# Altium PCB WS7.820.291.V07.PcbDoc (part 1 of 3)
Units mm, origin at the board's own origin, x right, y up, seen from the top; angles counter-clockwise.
Board outline 240.26 x 41.75 mm, 4 copper layers (Top Layer, S2, S3, Bottom Layer); 262 components, 157 nets, 756 pads, 1428 vias.
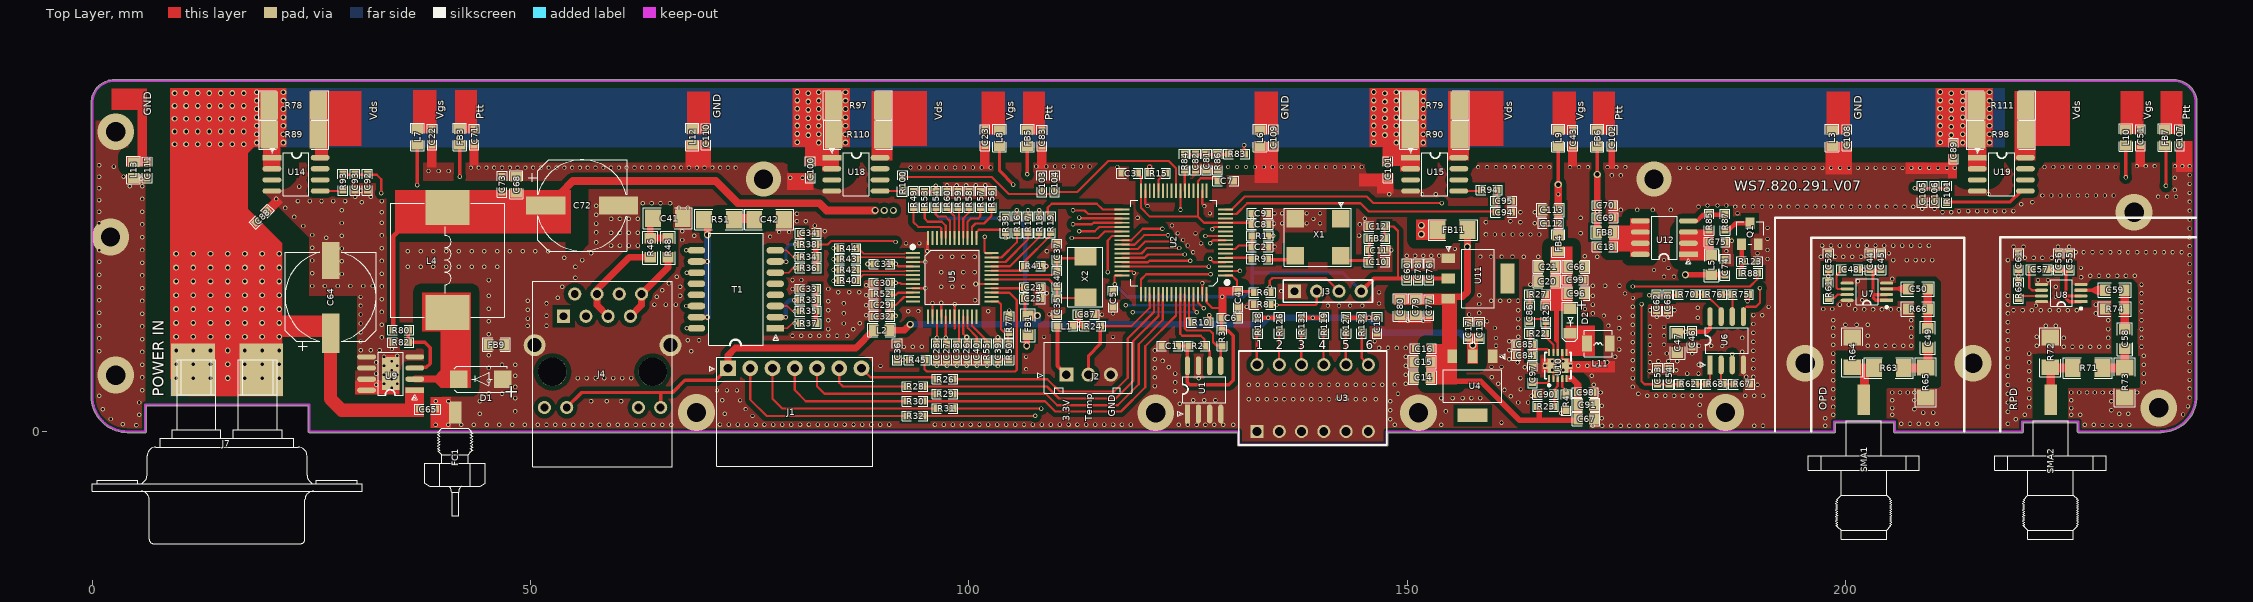
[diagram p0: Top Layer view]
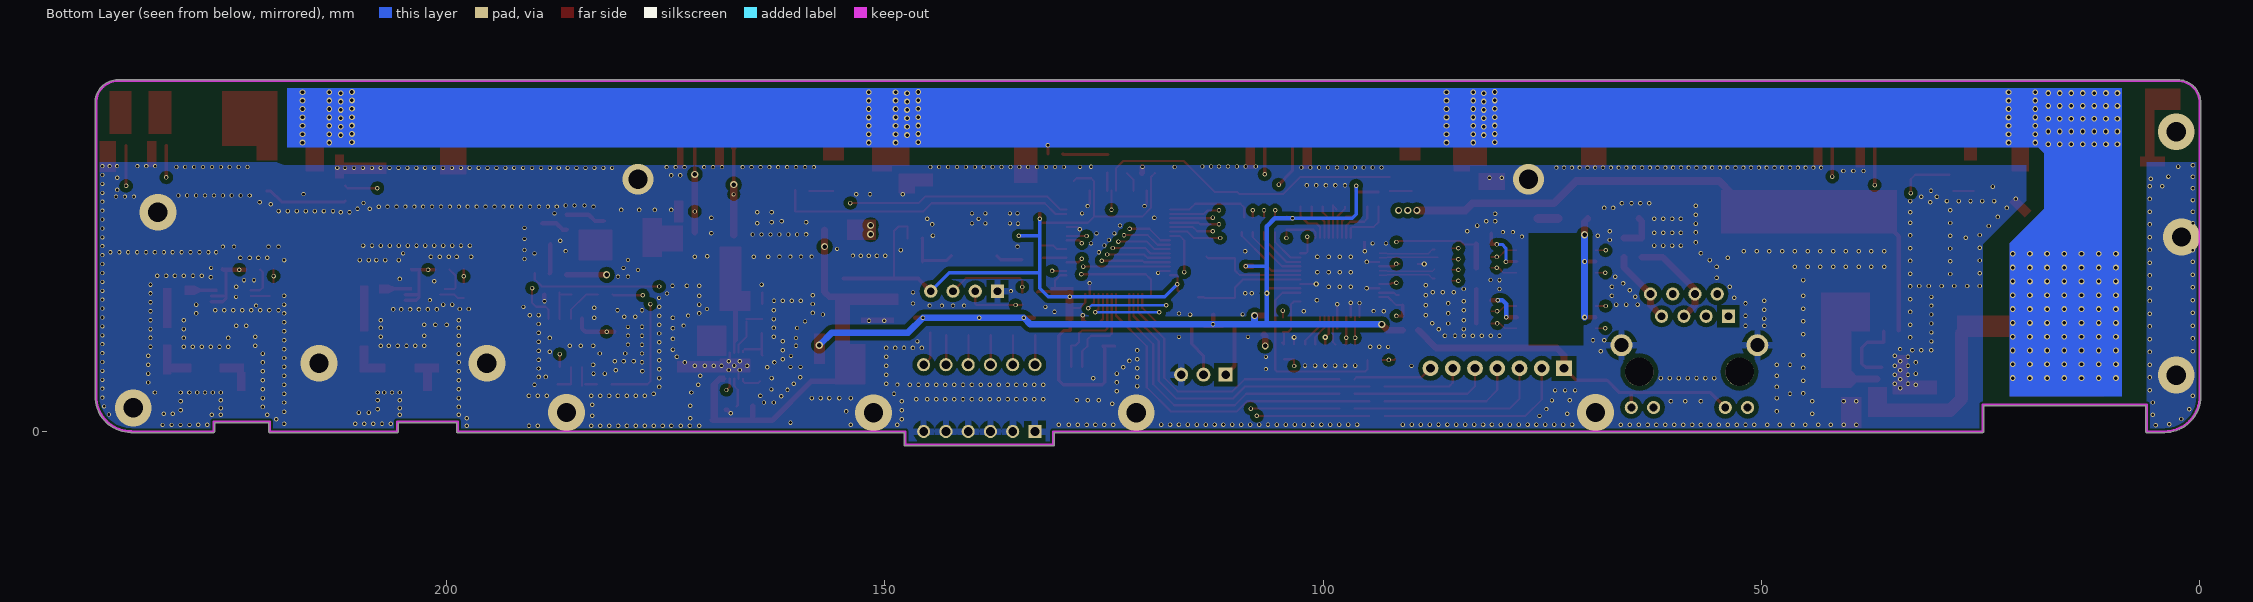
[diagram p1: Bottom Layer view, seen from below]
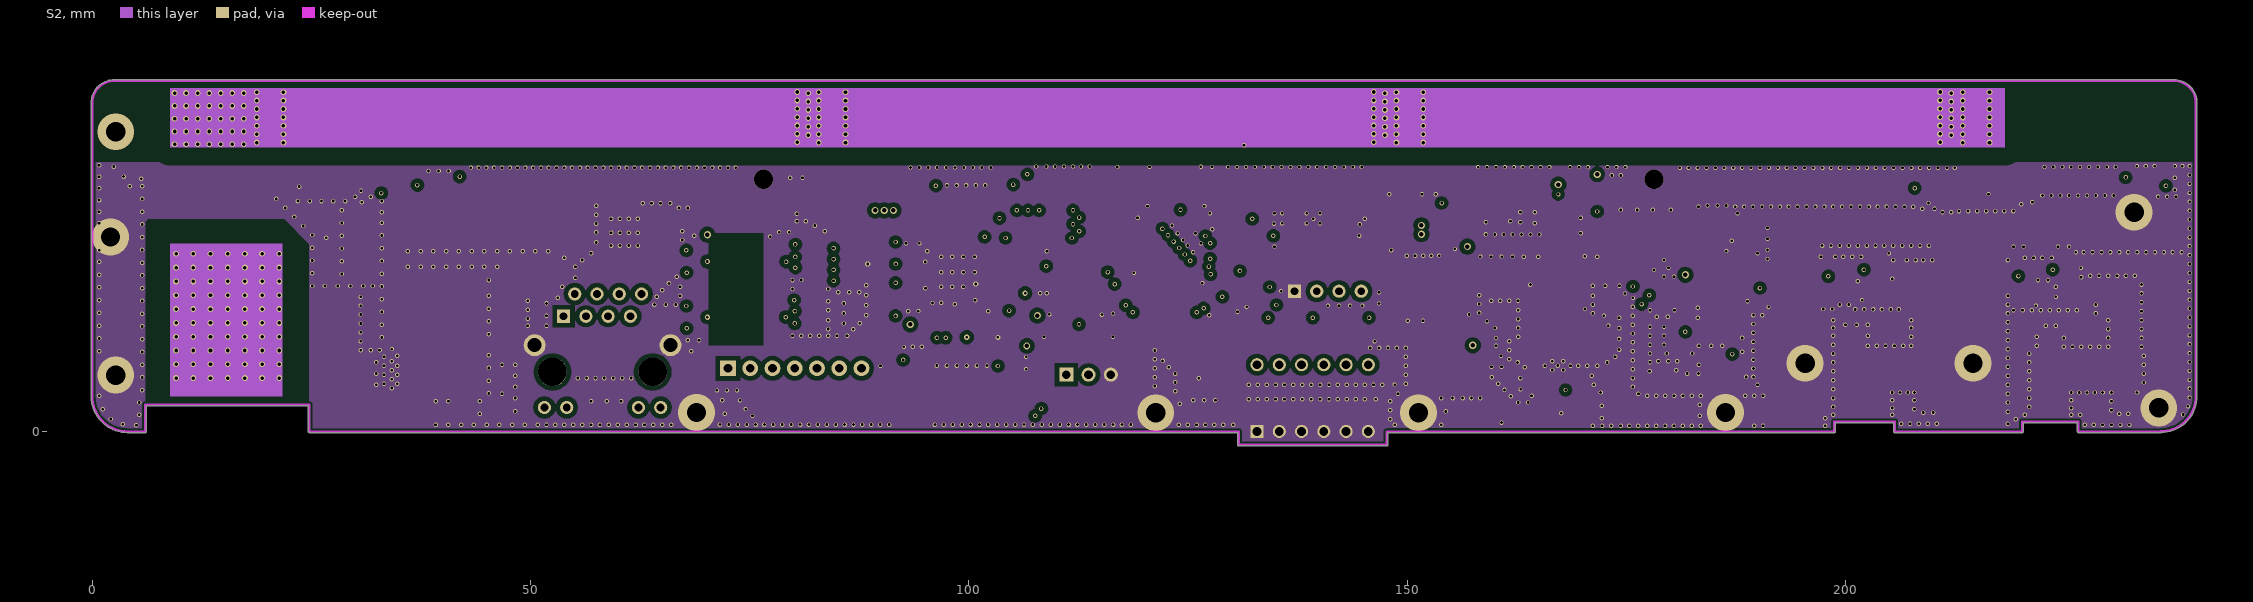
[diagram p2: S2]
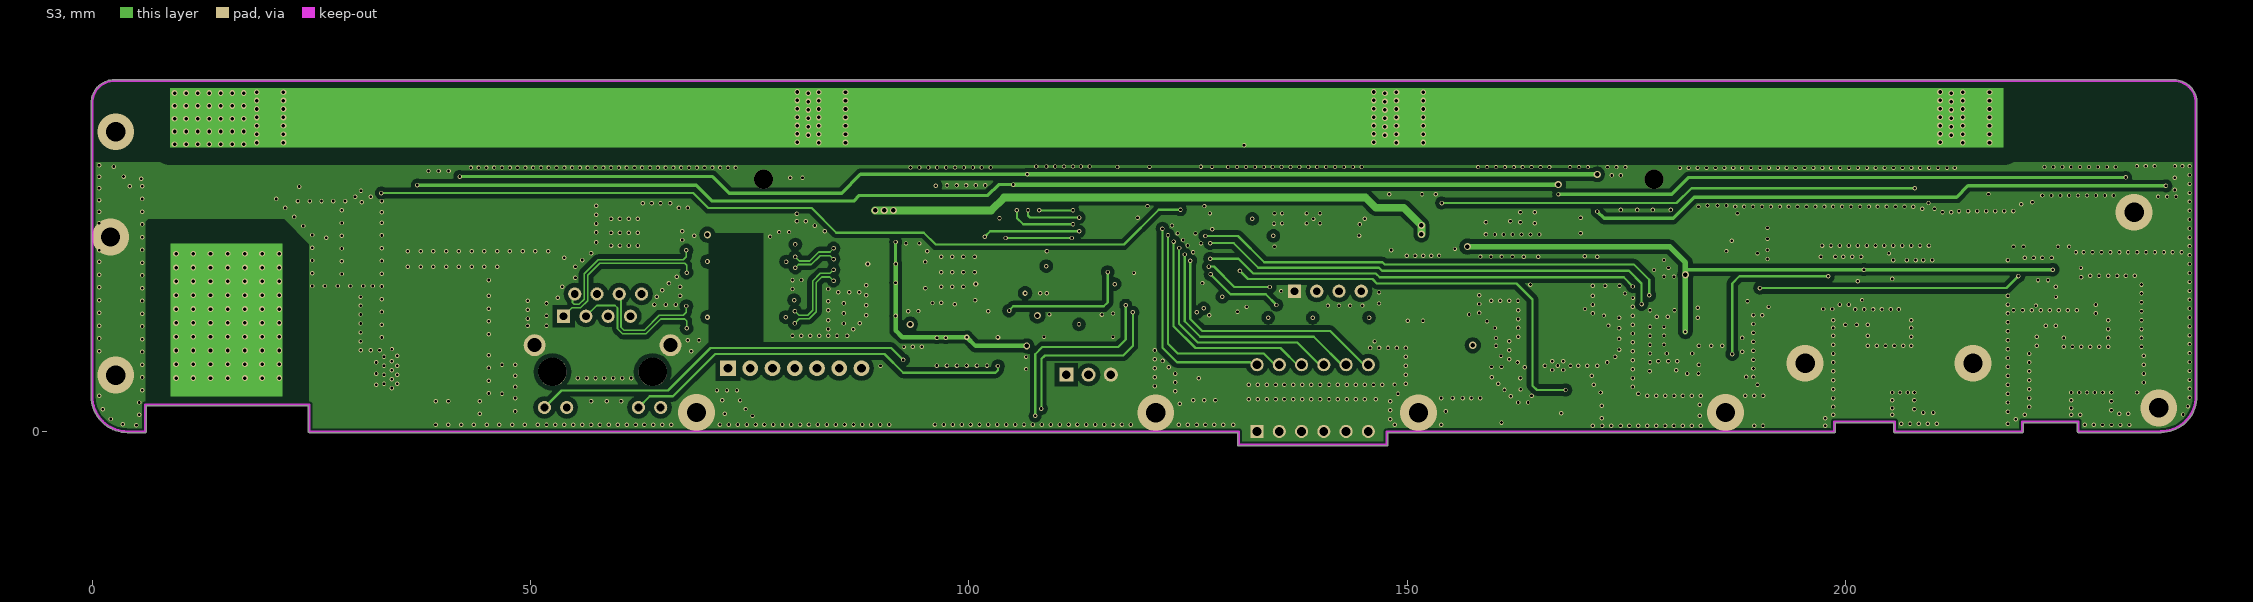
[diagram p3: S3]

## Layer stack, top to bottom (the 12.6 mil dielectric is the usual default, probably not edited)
Top Layer: signal copper 0.0356
Dielectric: core 0.32, FR-4, Dk 4.8
S2: signal copper 0.0356
Dielectric: prepreg 0.32, FR-4, Dk 4.8
S3: signal copper 0.0356
Dielectric: core 0.32, FR-4, Dk 4.8
Bottom Layer: signal copper 0.0356

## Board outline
4.008,-0.127 6.026,-0.127 ccw(c6.026,0) 6.153,0 6.153,2.921 24.638,2.921 24.638,0 ccw(c24.765,0) 24.766,-0.127 130.662,-0.127 130.662,-1.5 ccw(c130.789,-1.5) 130.789,-1.627 147.689,-1.627 ccw(c147.689,-1.5) 147.816,-1.5 147.816,-0.127 198.755,-0.127 ccw(c198.755,0) 198.882,0 198.882,1.019 205.536,1.019 205.536,0 ccw(c205.664,0) 205.664,-0.127 220.193,-0.127 ccw(c220.193,0) 220.32,0 220.32,1.019 226.491,1.019 226.491,0 ccw(c226.619,0) 226.619,-0.127 236,-0.127 ccw(c236,0) 236.057,-0.114 ccw(c236,4.013) 240.127,4.013 240.127,37.503 ccw(c237.508,37.503) 237.544,40.122 ccw(c237.508,40) 237.508,40.127 2.503,40.127 ccw(c2.503,37.492) -0.133,37.492 ccw(c-0.005,37.492) -0.127,37.457 -0.127,4.039 ccw(c0,4.039) -0.119,3.994 ccw(c4.008,4)

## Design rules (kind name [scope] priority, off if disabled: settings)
Clearance Clearance_4 [InNet('28VIN') vs (InPolygon)] p1: gap=2.032
Clearance Clearance_3 [(InPolygon) vs isfill] p2: gap=1.016
Clearance Clearance_2 [All vs OnLayer('Keep-Out Layer')] p3: gap=0.254
Clearance Clearance_1 [All vs (InPolygon)] p4: gap=0.5
Clearance [All] p5: gap=0.203
DiffPairsRouting DiffPair_DiffPairsRouting [All] p1: maxlimit=0.254 minlimit=0.216 mostfreqgap=0.216 maxuncoupledlength=12.7
DiffPairsRouting [All] p2: maxlimit=0.254 minlimit=0.254 mostfreqgap=0.254 maxuncoupledlength=12.7
HoleSize [All] p1: absolutevalues=TRUE maxlimit=76.2 minlimit=0.025 maxpercent=80.000 minpercent=20.000
HoleToHoleClearance [All] p1: gap=0.203 allowstackedmicrovias=TRUE
MatchedLengths DiffPair_MatchedLengths [All] p1: tolerance=25.4 checknetsindiffpair=FALSE checkdiffpairvsdiffpair=TRUE checkothers=FALSE
MinimumSolderMaskSliver [All] p1: minsoldermaskwidth=0
PlaneConnect [isvia] p1: planeconnectstyle=Direct reliefexpansion=0.508 reliefentries=4 reliefconductorwidth=0.254 reliefairgap=0.254
PlaneConnect PlaneConnect_1 [All] p2: planeconnectstyle=Relief reliefexpansion=0.508 reliefentries=4 reliefconductorwidth=0.762 reliefairgap=0.254
PolygonConnect PolygonConnect_1 [isvia] p1: connectstyle=Direct reliefconductorwidth=0.254 reliefentries=4 polygonreliefangle="90 Angle"
PolygonConnect [OnLayer('Bottom Layer')] p2: connectstyle=Relief reliefconductorwidth=0.762 reliefentries=4 polygonreliefangle="90 Angle"
PolygonConnect PolygonConnect_2 [All] p3: connectstyle=Direct reliefconductorwidth=0.254 reliefentries=4 polygonreliefangle="90 Angle"
RoutingVias [All] p1: holewidth=0.305 width=0.406 viastyle="Through Hole" minholewidth=0.305 minwidth=0.381 maxholewidth=0.711 maxwidth=1.27
SilkToSilkClearance [All] p1: silktosilkclearance=0
SilkscreenOverComponentPads [All] p1: minsilkscreentomaskgap=0
SolderMaskExpansion [All] p1: expansion=0.102
Width DiffPair_Width [All] p1: maxlimit=2.54 minlimit=0.191 preferedwidth=0.191
Width [All] p2: maxlimit=1 minlimit=0.191 preferedwidth=0.254 midlayer1_maxwidth=0.254 midlayer2_maxwidth=0.254 minimp=50.000000 maximp=50.000000 favimp=50.000000
21 further rules are at their usual default settings.

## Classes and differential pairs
component class 1-MCU: C1 C2 C3 C4 C5 C6 C7 C8 C9 C10 C11 C12 C87 FB2 J1 J2 J3 L1 L2 R1 R2 R3 R6 R8 R9 R10 R15 R16 R17 R18 R19 R24 R26 R28 R29 R30 R31 R32 R77 R118 R119 R126 R127 R131 R132 TP3 U1 U2 U3 X1
component class 2-RJ45: C24 C25 C26 C27 C28 C29 C30 C31 C32 C33 C34 C35 C36 C37 C38 C39 C40 C41 C42 FB1 FB9 J4 R33 R34 R35 R36 R37 R38 R39 R40 R41 R42 R43 R44 R45 R46 R47 R48 R49 R50 R51 R52 R53 R54 R55 R56 R57 R58 R59 R60 T1 U5 X2
component class 4-POWER: C13 C14 C15 C16 C17 C18 C19 C20 C21 C22 C23 C43 C51 C60 C64 C65 C66 C67 C68 C69 C70 C71 C72 C73 C74 C75 C76 C77 C78 C79 C80 C81 C82 C83 C84 C85 C86 C88 C89 C90 C91 C92 C93 C94 C95 C96 C97 C98 C99 C100 C101 C102 C103 C104 C105 C106 C107 C108 C109 C110 C111 C112 C113 C? D1 D2 FB3 FB4 FB5 FB6 FB7 FB8 FB11 FC1 J7 L3 L4 L5 L6 L7 L8 L9 L10 L11 L12 L13 Q1 R4 R22 R23 R25 R27 R78 R79 R80 R82 R83 R84 R85 R86 R87 R88 R89 R90 R93 R94 R97 R98 R100 R101 R110 R111 R123 U4 U9 U10 U11 U12 U13 U14 U15 U18 U19
component class 3-RF: C44 C45 C46 C47 C48 C49 C50 C52 C53 C54 C55 C56 C57 C58 C59 C61 C62 C63 C118 C119 C120 C122 C123 C124 C125 C126 C127 D3 Q2 Q3 R61 R62 R63 R64 R65 R66 R67 R68 R69 R70 R71 R72 R73 R74 R75 R76 R137 R138 R139 R140 R141 R142 R143 R144 R145 R146 R147 R148 SMA1 SMA2 U6 U7 U8
differential pair RX1: +RX1_P -RX1_N
differential pair RX: +RX_P -RX_N
differential pair TX1: +TX1_P -TX1_N
differential pair TX: +TX_P -TX_N
differential pair W5500_RX1: +W5500_RX1_P -W5500_RX1_N
differential pair W5500_TX1: +W5500_TX1_P -W5500_TX1_N

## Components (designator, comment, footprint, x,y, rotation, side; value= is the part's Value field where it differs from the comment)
C1 "0.1uF" C0603#1 122.936,9.745 r0 top
C2 "0.1uF" C0603#1 133.194,21.051 r180 top
C3 "0.1uF" C0603#1 118.364,29.464 r0 top
C4 "0.1uF" C0603#1 130.717,15.113 r90 top
C5 "0.1uF" C0603#1 116.459,15.113 r90 top
C6 "0.1uF" C0603#1 129.794,12.954 r180 top
C7 "0.1uF" C0603#1 129.308,28.575 r180 top
C8 "0.1uF" C0603#1 133.194,23.622 r180 top
C9 "10uF/6.3V" C0603#1 133.192,24.892 r180 top
C10 "10uF/6.3V" C0603#1 146.566,19.335 r180 top
C11 "0.1uF" C0603#1 146.566,20.677 r0 top
C12 "0.1uF" C0603#1 146.58,23.374 r180 top
C13 "0.1uF" C0603#2 158.242,11.557 r90 top
C14 "10uF/10V" C0805#1 151.74,6.147 r0 top
C15 "10uF/10V" C0805#1 151.74,7.925 r0 top
C16 "0.1uF" C0603#2 151.841,9.449 r180 top
C17 "10uF/6.3V" C0603#2 156.972,11.557 r90 top
C18 "0.1uF" C0603#2 172.593,21.082 r180 top
C19 "10uF/6.3V" C0603#2 146.558,12.122 r270 top
C20 "10uF/10V" C0805#1 165.964,17.145 r0 top
C21 "10uF/10V" C0805#1 165.964,18.796 r0 top
C22 "0.1uF" C0603#2 38.735,33.604 r90 top
C23 "0.1uF" C0603#2 101.854,33.528 r90 top
C24 "0.1uF" C0603#1 107.26,16.446 r180 top
C25 "10uF/6.3V" C0603#1 107.26,15.144 r180 top
C26 "0.1uF" C0603#1 99.767,9.08 r90 top
C27 "0.1uF" C0603#1 97.481,9.08 r90 top
C28 "0.1uF" C0603#1 96.338,9.08 r90 top
C29 "0.1uF" C0603#1 90.09,14.414 r0 top
C30 "0.1uF" C0603#1 90.09,16.954 r0 top
C31 "0.1uF" C0603#1 90.09,19.113 r0 top
C32 "10uF/6.3V" C0603#1 90.09,13.144 r0 top
C33 "10nF" C0603#1 81.661,16.256 r0 top
C34 "22nF" C0603#1 81.686,22.612 r180 top
C35 "18pF" C0603#1 110.054,14.255 r90 top
C36 "1000pF" C0603#1 91.821,9.08 r270 top
C37 "18pF" C0603#1 110.054,20.478 r270 top
C38 "4.7uF" C0603#1 98.624,9.08 r90 top
C39 "1000pF" C0603#1 103.323,9.08 r270 top
C40 "10nF" C0603#1 100.91,9.08 r90 top
C41 "1000pF/2KV" C1206 65.659,24.308 r180 top
C42 "1000pF/2KV" C1206 77.212,24.181 r180 top
C43 "0.1uF" C0603#2 168.91,33.477 r90 top
C44 "100pF" C0603#1 202.819,19.38 r90 top
C45 "0.1uF" C0603#1 204.089,19.38 r90 top
C46 "0.1uF" C0603#1 182.501,10.516 r270 top
C47 "10uF/10V" C0805#2 180.85,10.109 r270 top
C48 "0.1uF" C0603#1 200.533,18.457 r0 top
C49 "100pF" C0805#2 209.423,10.668 r90 top
C50 "100pF" C0805#2 208.296,16.256 r180 top
C51 "0.1uF" C0603#2 233.68,33.528 r90 top
C52 "0.1uF" C0603#1 198.069,19.38 r270 top
C53 "10uF/6.3V" C0603#1 178.602,6.311 r270 top
C54 "0.1uF" C0603#1 179.872,6.311 r270 top
C55 "100pF" C0603#1 225.584,19.38 r90 top
C56 "0.1uF" C0603#1 224.314,19.38 r90 top
C57 "0.1uF" C0603#1 222.123,18.457 r0 top
C58 "100pF" C0805#2 231.902,10.541 r90 top
C59 "100pF" C0805#2 230.759,16.129 r180 top
C60 "10uF/6.3V" C0603#2 149.987,18.212 r90 top
C61 "0.1uF" C0603#1 219.761,19.38 r270 top
C62 "10uF/6.3V" C0603#1 178.475,14.693 r90 top
C63 "0.1uF" C0603#1 179.745,14.693 r90 top
C64 "100uF/63V" ECAP2SM_10R4x10R4#1 27.178,15.367 r90 top
C65 "0.1uF" C0603#1 38.227,2.54 r180 top
C66 "10uF/10V" C0805#1 169.291,18.796 r180 top
C67 "10uF/10V" C0805#1 170.434,1.418 r180 top
C68 "10uF/10V" C0805#1 48.362,28.143 r270 top
C69 "0.1uF" C0603#2 172.593,24.384 r0 top
C70 "10uF" C0603#2 172.593,25.781 r0 top
C71 "0.1uF" C0603#2 43.561,33.604 r270 top
C72 "1000uF/16V" ECAP2SM_10R4x10R4#2 55.88,25.781 r0 top
C73 "0.1uF" C0603#1 46.736,28.194 r270 top
C74 "1uF" C0603#1 186.294,18.726 r90 top
C75 "0.1uF" C0603#1 185.37,21.602 r0 top
C76 "1uF" C0603#1 152.527,18.212 r270 top
C77 "0.1uF" C0603#1 152.502,14.148 r90 top
C78 "10uF/6.3V" C0603#2 151.257,18.212 r90 top
C79 "10uF/10V" C0805#1 150.978,14.148 r90 top
C80 "10uF/10V" C0805#1 149.2,14.148 r90 top
C81 "10uF/6.3V" C0603#1 127.115,30.743 r90 top
C82 "0.1uF" C0603#1 125.845,30.743 r90 top
C83 "0.1uF" C0603#2 108.331,33.477 r270 top
C84 "0.1uF" C0603#2 163.398,8.661 r0 top
C85 "0.1uF" C0603#2 163.398,9.931 r0 top
C86 "10pF" C0603#2 163.999,13.437 r270 top
C87 "0.1uF" C0603#2 113.411,13.335 r0 top
C88 "0.1uF" C0603#1 19.304,24.511 r225 top
C89 "0.1uF" C0603#1 212.344,32.004 r90 top
C90 "0.1uF" C0603#2 165.811,4.216 r180 top
C91 "10uF/10V" C0805#1 170.434,3.048 r180 top
C92 "10uF/6.3V" C0603#1 31.369,28.448 r90 top
C93 "0.1uF" C0603#1 29.972,28.448 r90 top
C94 "10uF/6.3V" C0603#1 161.036,25.019 r180 top
C95 "0.1uF" C0603#1 161.036,26.314 r180 top
C96 "10uF/10V" C0805#1 169.291,15.748 r180 top
C97 "10NF" C0603#2 164.321,6.477 r90 top
C98 "1uF" C0603#2 170.332,4.445 r0 top
C99 "0.1uF" C0603#2 169.189,17.272 r0 top
C100 "0.1uF" C0603#1 81.915,29.845 r90 top
C101 "0.1uF" C0603#1 147.828,29.845 r90 top
C102 "0.1uF" C0603#2 173.355,33.477 r270 top
C103 "10uF/6.3V" C0603#1 108.331,28.245 r270 top
C104 "0.1uF" C0603#1 109.779,28.245 r270 top
C105 "10uF/6.3V" C0603#1 208.788,27.051 r90 top
C106 "0.1uF" C0603#1 210.185,27.051 r90 top
C107 "0.1uF" C0603#2 238.125,33.528 r270 top
C108 "0.1uF" C0603#2 200.182,33.498 r90 top
C109 "0.1uF" C0603#2 134.777,33.498 r90 top
C110 "0.1uF" C0603#2 70.007,33.625 r90 top
C111 "0.1uF" C0603#2 6.253,29.84 r90 top
C112 "0.1uF" C0603#2 166.37,23.749 r180 top
C113 "10uF/10V" C0805#1 166.37,25.273 r0 top
D1 "SS36" DO-214AC 44.323,5.969 r180 top
D2 "SL02" SL02 168.605,12.598 r270 top
FB1 "FB" L0805#1 106.752,12.128 r270 top
FB2 "FB_0603" L0603 146.58,22.032 r0 top
FB3 "FB_0805" L0805#2 41.91,33.604 r90 top
FB4 "FB" L0805#2 167.259,21.463 r90 top
FB5 "FB_0805" L0805#2 106.68,33.477 r90 top
FB6 "FB_0805" L0805#2 171.704,33.477 r90 top
FB7 "FB_0805" L0805#2 236.474,33.528 r90 top
FB8 "FB" L0805#2 172.593,22.733 r180 top
FB9 "open" L0805#2 46.101,9.906 r180 top
FB11 "FB_1206" L1206 155.194,22.987 r0 top
FC1 "CT52-2-63V-2200PF" FC-M4 41.402,2.159 r270 top
J1 "open" "KF2510-7P -2R54-17R8x6R0-wanzhen" 72.517,7.208 r0 top
J2 "XH2.54-3P" XH2.54mm-10R0x7R0--zhizhen 111.125,6.477 r0 top
J3 "Header 4" HDR1X4 137.16,16.002 r0 top
J4 "RJ45插座" RJ45TH-1x1-2R54-LED 58.213,14.414 r0 top
J7 "DB2" DB2TM-VM 15.367,7.017 r180 top locked
L1 "FB_0603" L0603 110.973,12.014 r0 top
L2 "FB_0805" L0805#2 90.043,11.557 r0 top
L3 "FB" L0805#2 198.501,33.477 r90 top
L4 "100uH" PL2SM-12R5x12R5 40.513,19.558 r180 top
L5 "FB_0805" L0805#1 184.735,18.98 r90 top
L6 "FB" L0805#2 133.223,33.477 r90 top
L7 "FB" L0805#2 37.084,33.604 r90 top
L8 "FB" L0805#2 103.505,33.477 r90 top
L9 "FB" L0805#2 167.259,33.477 r90 top
L10 "FB" L0805#2 232.029,33.528 r90 top
L11 "4.7uH" PL2SM-3R0x3R0 171.831,10.033 r180 top
L12 "FB" L0805#2 68.453,33.604 r90 top
L13 "FB" L0805#2 4.699,29.82 r90 top
Q1 "MMBT2222" SOT23-3 189.128,22.572 r270 top
R1 "4.7K" R0603 133.194,22.322 r0 top
R2 "4.7K" R0603 126.031,9.745 r180 top
R3 "4.7K" R0603 128.871,10.668 r90 top
R4 "10K" R0603 168.148,3.302 r270 top
R6 "4.7K" R0603 133.477,15.875 r180 top
R8 "4.7K" R0603 133.477,14.478 r0 top
R9 "30Ω" R0603 133.207,19.665 r180 top
R10 "1K" R0603 126.365,12.446 r180 top
R15 "1K" R0603 121.539,29.464 r0 top
R16 "30Ω" R0603 105.486,23.597 r270 top
R17 "30Ω" R0603 106.756,23.597 r270 top
R18 "30Ω" R0603 108.026,23.597 r270 top
R19 "30Ω" R0603 109.296,23.597 r270 top
R22 "150KΩ" R0603 164.922,11.201 r180 top
R23 "10Ω" R0603 165.811,2.87 r0 top
R24 "4.7K" R0603 114.148,12.014 r0 top
R25 "619KΩ" R0603 165.845,13.437 r270 top
R26 "300Ω" R0603 97.282,5.969 r0 top
R27 "100KΩ" R0603 164.922,15.646 r180 top
R28 "300Ω" R0603 93.853,5.131 r0 top
R29 "300Ω" R0603 97.282,4.293 r0 top
R30 "300Ω" R0603 93.853,3.454 r0 top
R31 "300Ω" R0603 97.282,2.616 r0 top
R32 "300Ω" R0603 93.853,1.778 r0 top
R33 "0Ω" R0603 81.661,14.986 r180 top
R34 "49.9Ω" R0603 81.686,19.914 r0 top
R35 "82Ω" R0603 81.686,13.722 r180 top
R36 "49.9Ω" R0603 81.686,18.669 r0 top
R37 "82Ω" R0603 81.686,12.325 r180 top
R38 "10Ω" R0603 81.686,21.342 r0 top
R39 "4.7K" R0603 104.165,23.597 r90 top
R40 "30Ω" R0603 86.204,17.208 r180 top
R41 "4.7K" R0603 107.26,18.859 r0 top
R42 "30Ω" R0603 86.204,18.435 r180 top
R43 "30Ω" R0603 86.204,19.663 r180 top
R44 "30Ω" R0603 86.204,20.891 r180 top
R45 "300Ω" R0603 94.107,8.156 r0 top
R46 "75Ω" R0805 63.652,20.967 r270 top
R47 "1M" R0603 110.054,17.385 r270 top
R48 "75Ω" R0805 65.684,20.967 r270 top
R49 "4.7K" R0603 93.697,26.479 r90 top
R50 "300Ω" R0603 104.593,9.08 r90 top
R51 "75Ω" R1206 71.497,24.181 r180 top
R52 "12.4K" R0603 90.09,15.684 r0 top
R53 "4.7K" R0603 94.967,26.479 r90 top
R54 "4.7K" R0603 96.237,26.479 r90 top
R55 "1K" R0603 102.053,9.08 r90 top
R56 "1K" R0603 102.587,26.479 r270 top
R57 "1K" R0603 101.317,26.479 r270 top
R58 "1K" R0603 100.047,26.479 r270 top
R59 "1K" R0603 98.777,26.479 r270 top
R60 "1K" R0603 97.507,26.479 r270 top
R61 "1K" R0603 198.069,16.078 r90 top
R62 "0Ω" R0603 182.031,5.388 r180 top
R63 "240Ω" R1206 204.978,7.239 r0 top
R64 "62Ω" R1206 200.787,9.017 r270 top
R65 "62Ω" R1206 209.169,5.588 r90 top
R66 "51Ω" R0805 208.296,13.97 r0 top
R67 "open" R0603 188.185,5.388 r180 top
R68 "0Ω" R0603 185.079,5.388 r180 top
R69 "1K" R0603 219.761,16.078 r90 top
R70 "0Ω" R0603 181.904,15.616 r180 top
R71 "" R1206 227.66,7.239 r0 top
R72 "62Ω" R1206 223.393,9.017 r270 top
R73 "62Ω" R1206 231.902,5.588 r90 top
R74 "51Ω" R0805 230.759,13.97 r0 top
R75 "open" R0603 188.058,15.616 r180 top
R76 "0Ω" R0603 184.981,15.616 r180 top
R77 "0Ω" R0603 104.593,12.192 r270 top
R78 "0.004" R2512 22.987,37.186 r0 top (schematic designator R45)
R79 "0.004" R2512 153.162,37.186 r0 top (schematic designator R47)
R80 "6.2K" R0603 35.179,11.557 r180 top
R82 "2K" R0603 35.179,10.16 r180 top
R83 "24K" R0603 130.556,31.666 r180 top
R84 "1K" C0603#1 124.587,30.743 r90 top
R85 "10K" R0603 184.447,23.888 r270 top
R86 "1.5K" R0603 128.385,30.743 r90 top
R87 "0Ω" R0603 186.294,23.888 r90 top
R88 "1K" R0603 189.099,18.056 r180 top
R89 "0.004" R2512 22.987,33.884 r0 top (schematic designator R198)
R90 "0.004" R2512 153.162,33.884 r0 top (schematic designator R199)
R93 "1K" R0603 28.575,28.448 r90 top
R94 "1K" R0603 159.385,27.559 r0 top
R97 "0.004" R2512 87.376,37.186 r0 top (schematic designator R202)
R98 "0.004" R2512 217.78,33.884 r0 top (schematic designator R102)
R100 "1K" R0603 92.408,28.299 r90 top
R101 "1K" R0603 211.582,27.051 r90 top
R110 "0.004" R2512 87.376,33.884 r0 top (schematic designator R92)
R111 "0.004" R2512 217.78,37.186 r0 top (schematic designator R93)
R118 "4.7K" R0603 133.016,12.122 r90 top
R119 "4.7K" R0603 140.509,12.122 r90 top
R123 "1K" R0603 189.099,19.395 r180 top
R126 "4.7K" R0603 135.429,12.122 r90 top
R127 "4.7K" R0603 143.049,12.122 r90 top
R131 "4.7K" R0603 137.969,12.122 r90 top
R132 "4.7K" R0603 144.827,12.122 r90 top
SMA1 "SMA-50KFD-4" SMA-50KFD-4 202.057,3.611 r270 top (schematic designator SMA2)
SMA2 "SMA-50KFD-4" SMA-50KFD-4 223.376,3.611 r270 top locked (schematic designator SMA3)
T1 "HX1188NL" SOP16-1R27-7R11x12R7 73.428,16.217 r180 top locked
U1 "AT24C02N" SOIC8_1R27_3R9x4R9 126.848,4.75 r90 top
U2 "STM32F103RCT6" LQFP64-0R50-10x10 123.35,21.545 r90 top locked
U3 "2.54mm-6P" CON12TM-2R54-2X6-BOMA 139.239,3.809 r0 top
U4 "LM1117S-3.3" SOT-223 157.48,5.207 r180 top
U5 "W5500" TQFN48-0R5-7X7 98.116,17.589 r0 top locked
U6 "LM358" SOIC8_1R27_3R9x4R9 186.476,10.35 r90 top
U7 "AD8361ARMZ" micro_SOIC8-0R65-3x3 202.477,15.942 r180 top
U8 "AD8361ARMZ" micro_SOIC8-0R65-3x3 224.656,15.783 r180 top locked
U9 "LM2576HVDP-ADJ" SOIC8_1R27_3R9x4R9-1 34.036,6.604 r180 top
U10 "TPS63700DRCR" VSON10-0R5-3x3 167.208,7.518 r90 top
U11 "LM1117S-3.3" SOT-223 158.09,17.45 r270 top
U12 "IRF7240TR" SOIC8_1R27_3R9x4R9 179.364,22.11 r180 top
U14 "MAX4080TASA" SOIC8_1R27_3R9x4R9 23.241,29.337 r0 top
U15 "MAX4080TASA" SOIC8_1R27_3R9x4R9 153.162,29.337 r0 top
U18 "MAX4080TASA" SOIC8_1R27_3R9x4R9 87.122,29.337 r0 top
U19 "MAX4080TASA" SOIC8_1R27_3R9x4R9 217.805,29.337 r0 top
X1 "8M" CRY4SM-5R0x7R0 139.827,22.149 r180 top
X2 "25M" CRY2SM-6R0x3R5 113.306,17.639 r270 top

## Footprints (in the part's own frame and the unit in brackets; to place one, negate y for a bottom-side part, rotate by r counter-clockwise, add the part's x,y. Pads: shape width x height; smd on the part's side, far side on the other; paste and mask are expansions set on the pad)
C0603#1 [mm]
  rect 0.9x0.8 smd: 1(-0.85,0) 2(0.85,0)
  silkscreen extent -1.47,-0.55 1.47,0.55
C0603#2 [mm]
  rect 0.9x0.8 smd: 1(0.85,0) 2(-0.85,0)
  silkscreen extent -1.47,-0.55 1.47,0.55
C0805#1 [mm]
  rect 1.1x1.3 smd: 1(-0.9,0) 2(0.9,0)
  silkscreen extent -1.57,-0.76 1.57,0.76
C0805#2 [mm]
  rect 1.2x1.3 smd: 1(-1.1,0) 2(1.1,0)
  silkscreen extent -1.88,-0.84 1.88,0.84
C1206 [mm]
  rect 1.8x2 smd: 1(-1.7,0) 2(1.7,0)
  silkscreen extent -2.79,-1.19 2.79,1.19
CON12TM-2R54-2X6-BOMA [mm]
  rect 1.5x1.5 hole 1: 1(-6.35,-3.81)
  round 1.5 hole 1: 2(-6.35,3.81) 3(-3.81,-3.81) 4(-3.81,3.81) 5(-1.27,-3.81) 6(-1.27,3.81) 7(1.27,-3.81) 8(1.27,3.81) 9(3.81,-3.81) 10(3.81,3.81) 11(6.35,-3.81) 12(6.35,3.81)
  silkscreen extent -8.45,-5.36 8.45,5.36
CRY2SM-6R0x3R5 [mm]
  rect 2x2.5 smd: 1(-2.3,0) 2(2.3,0)
  silkscreen extent -3.4,-2.03 3.4,1.97
CRY4SM-5R0x7R0 [mm]
  rect 2x2 smd: 1(-2.6,-2.1) 2(2.6,-2.1) 3(2.6,2.1) 4(-2.6,2.1)
  silkscreen extent -3.81,-4.02 3.81,3.33
DB2TM-VM [mm] "DB2"
  rect 5x6 smd: 1(-3.9,0) 2(3.9,0)
  Top Overlay keep-out lines w0.1: -1.298,2.812 -5.698,2.812
  silkscreen extent -15.4,-1.19 15.4,19.81
DO-214AC [mm]
  rect 2x2 smd: 1(-2.5,0) 2(2.5,0)
  silkscreen extent -3.04,-1.49 3.04,1.49
ECAP2SM_10R4x10R4#1 [mm]
  rect 4.5x2 smd: 1(-4.15,0)
  rect 4.191x2 smd: 2(4.15,0)
  silkscreen extent -6.16,-5.21 5.08,5.21
ECAP2SM_10R4x10R4#2 [mm]
  rect 4.5x2 smd: 1(-4.15,0) 2(4.15,0)
  silkscreen extent -6.16,-5.21 5.08,5.21
FC-M4 [mm] "一对"
  rect 2.5x1.4 smd: 1(0,0)
  silkscreen extent 1.8,-3.48 11.77,3.44
HDR1X4 [mm] "Connector; Header; 4 Position"
  rect 1.5x1.5 hole 0.9: 1(0,0)
  round 1.5 hole 0.9: 2(2.54,0) 3(5.08,0) 4(7.62,0)
  silkscreen extent -1.27,-1.27 8.89,1.27
"KF2510-7P -2R54-17R8x6R0-wanzhen" [mm]
  rect 1.8x1.8 hole 1: 1(0,0)
  round 1.8 hole 1: 2(2.54,0) 3(5.08,0) 4(7.62,0) 5(10.16,0) 6(12.7,0) 7(15.24,0)
  silkscreen extent -2.12,-11.2 16.56,1.24
L0603 [mm]
  rect 0.9x0.8 smd: 1(-0.85,0) 2(0.85,0)
  silkscreen extent -1.47,-0.55 1.47,0.55
L0805#1 [mm]
  rect 1.2x1.3 smd: 1(-1.1,0) 2(1.1,0)
  silkscreen extent -1.88,-0.84 1.88,0.84
L0805#2 [mm]
  rect 1.1x1.3 smd: 1(-0.9,0) 2(0.9,0)
  silkscreen extent -1.57,-0.76 1.57,0.76
L1206 [mm]
  rect 1.8x2 smd: 1(-1.7,0) 2(1.7,0)
  silkscreen extent -2.79,-1.19 2.79,1.19
LQFP64-0R50-10x10 [mm] "STM32F103RC"
  rect 0.22x1.7 smd: 1(-3.731,-5.941) 2(-3.231,-5.941) 3(-2.731,-5.941) 4(-2.231,-5.941) 5(-1.731,-5.941) 6(-1.231,-5.941) 7(-0.731,-5.941) 8(-0.231,-5.941) 9(0.269,-5.941) 10(0.769,-5.941) 11(1.269,-5.941) 12(1.769,-5.941) 13(2.269,-5.941) 14(2.769,-5.941) 15(3.269,-5.941) 16(3.769,-5.941) 33(3.769,5.861) 34(3.269,5.861) 35(2.769,5.862) 36(2.269,5.862) 37(1.769,5.862) 38(1.269,5.862) 39(0.769,5.862) 40(0.269,5.862) 41(-0.231,5.862) 42(-0.731,5.862) 43(-1.231,5.862) 44(-1.731,5.862) 45(-2.231,5.862) 46(-2.731,5.862) 47(-3.231,5.862) 48(-3.731,5.861)
  rect 1.7x0.22 smd: 17(5.917,-3.793) 18(5.917,-3.293) 19(5.917,-2.793) 20(5.917,-2.293) 21(5.917,-1.793) 22(5.917,-1.293) 23(5.917,-0.793) 24(5.917,-0.293) 25(5.917,0.207) 26(5.917,0.707) 27(5.917,1.207) 28(5.917,1.707) 29(5.917,2.207) 30(5.917,2.707) 31(5.917,3.207) 32(5.917,3.707) 49(-5.886,3.713) 50(-5.886,3.213) 51(-5.886,2.713) 52(-5.886,2.213) 53(-5.886,1.713) 54(-5.886,1.213) 55(-5.886,0.713) 56(-5.886,0.213) 57(-5.886,-0.287) 58(-5.886,-0.787) 59(-5.886,-1.287) 60(-5.886,-1.787) 61(-5.886,-2.286) 62(-5.886,-2.786) 63(-5.886,-3.287) 64(-5.886,-3.786)
  silkscreen extent -4.92,-6.32 4.86,4.85
micro_SOIC8-0R65-3x3 [mm] "检波器"
  rect 1.5x0.35 smd: 1(-2.25,0.975)
  oval 1.5x0.35 smd: 2(-2.25,0.325) 3(-2.25,-0.325) 4(-2.25,-0.975) 5(2.25,-0.975) 6(2.25,-0.325) 7(2.25,0.325) 8(2.25,0.975)
  silkscreen extent -2.38,-1.5 1.23,1.87
PL2SM-3R0x3R0 [mm]
  rect 1.1x1.8 smd: 1(-1.3,0) 2(1.3,0)
  silkscreen extent -1.6,-1.5 1.6,1.5
PL2SM-12R5x12R5 [mm]
  rect 5x4 smd: 1(0,6) 2(0,-6)
  silkscreen extent -6.5,-6.5 6.5,6.5
R0603 [mm]
  rect 0.9x0.8 smd: 1(-0.85,0) 2(0.85,0)
  silkscreen extent -1.47,-0.55 1.47,0.55
R0805 [mm]
  rect 1.2x1.3 smd: 1(-1.1,0) 2(1.1,0)
  silkscreen extent -1.88,-0.84 1.88,0.84
R1206 [mm]
  rect 1.8x2 smd: 1(-1.7,0) 2(1.7,0)
  silkscreen extent -2.79,-1.19 2.79,1.19
R2512 [mm]
  rect 2x3.2 smd: 1(-2.8,0) 2(2.8,0)
  silkscreen extent -3.99,-1.7 3.91,1.7
RJ45TH-1x1-2R54-LED [mm]
  rect 1.5x1.5 hole 0.9: 1(-4.445,-1.27)
  round 1.5 hole 0.9: 2(-3.175,1.27) 3(-1.905,-1.27) 4(-0.635,1.27) 5(0.635,-1.27) 6(1.905,1.27) 7(3.175,-1.27) 8(4.445,1.27) 9(-6.63,-11.68) 10(-4.09,-11.68) 11(4.09,-11.68) 12(6.63,-11.68)
  round 2.5 hole 1.6: 13(-7.75,-4.57) 14(7.75,-4.57)
  round 3.25 hole 3.25 unplated: 15(-5.715,-7.62) 16(5.715,-7.62)
  silkscreen extent -7.94,-18.42 7.94,2.73
SL02 [mm]
  rect 1.2x1.5 smd: 1(-1.4,0) 2(1.4,0)
  silkscreen extent -2.16,-0.9 2.28,0.9
SMA-50KFD-4 [mm] "SMA-JB3C"
  rect 3.5x1.4 smd: 1(0,0.06)
  silkscreen extent 2.37,-6.29 15.9,6.41
SOIC8_1R27_3R9x4R9 [mm]
  rect 2.15x0.6 smd: 1(-2.75,1.905)
  oval 2.15x0.6 smd: 2(-2.75,0.635) 3(-2.75,-0.635) 4(-2.75,-1.905) 5(2.75,-1.905) 6(2.75,-0.635) 7(2.75,0.635) 8(2.75,1.905)
  silkscreen extent -3.02,-2.45 1.47,2.99
SOIC8_1R27_3R9x4R9-1 [mm]
  rect 2.15x0.6 smd: 1(-2.75,1.905)
  oval 2.15x0.6 smd: 2(-2.75,0.635) 3(-2.75,-0.635) 4(-2.75,-1.905) 5(2.75,-1.905) 6(2.75,-0.635) 7(2.75,0.635) 8(2.75,1.905)
  rect 2x3.8 smd: 9(0,0)
  silkscreen extent -3.02,-2.45 1.47,2.99
SOP16-1R27-7R11x12R7 [mm]
  rect 2x0.76 smd: 1(-4.5,4.445)
  oval 2x0.76 smd: 2(-4.5,3.175) 3(-4.5,1.905) 4(-4.5,0.635) 5(-4.5,-0.635) 6(-4.5,-1.905) 7(-4.5,-3.175) 8(-4.5,-4.445) 9(4.5,-4.445) 10(4.5,-3.175) 11(4.5,-1.905) 12(4.5,-0.635) 13(4.5,0.635) 14(4.5,1.905) 15(4.5,3.175) 16(4.5,4.445)
  silkscreen extent -4.84,-6.4 3.1,6.4
SOT23-3 [mm]
  rect 1.3x1 smd: 1(1.2,-0.95) 2(1.2,0.95) 3(-1.2,0)
  silkscreen extent -1.34,-1.5 1.2,1.5
SOT-223 [mm]
  rect 1.1x1.55 smd: 1(-2.3,-3.375) 2(0,-3.375) 3(2.3,-3.375)
  rect 3.45x1.55 smd: 4(0,3.375)
  silkscreen extent -3.7,-3.65 3.35,1.85
TQFN48-0R5-7X7 [mm]
  rect 1.6x0.22 smd: 1(-4.5,2.75) 2(-4.5,2.25) 3(-4.5,1.75) 4(-4.5,1.25) 5(-4.5,0.75) 6(-4.5,0.25) 7(-4.5,-0.25) 8(-4.5,-0.75) 9(-4.5,-1.25) 10(-4.5,-1.75) 11(-4.5,-2.25) 12(-4.5,-2.75) 25(4.5,-2.75) 26(4.5,-2.25) 27(4.5,-1.75) 28(4.5,-1.25) 29(4.5,-0.75) 30(4.5,-0.25) 31(4.5,0.25) 32(4.5,0.75) 33(4.5,1.25) 34(4.5,1.75) 35(4.5,2.25) 36(4.5,2.75)
  rect 0.22x1.6 smd: 13(-2.75,-4.5) 14(-2.25,-4.5) 15(-1.75,-4.5) 16(-1.25,-4.5) 17(-0.75,-4.5) 18(-0.25,-4.5) 19(0.25,-4.5) 20(0.75,-4.5) 21(1.25,-4.5) 22(1.75,-4.5) 23(2.25,-4.5) 24(2.75,-4.5) 37(2.75,4.5) 38(2.25,4.5) 39(1.75,4.5) 40(1.25,4.5) 41(0.75,4.5) 42(0.25,4.5) 43(-0.25,4.5) 44(-0.75,4.5) 45(-1.25,4.5) 46(-1.75,4.5) 47(-2.25,4.5) 48(-2.75,4.5)
  silkscreen extent -4.72,-3.06 3.06,3.65
VSON10-0R5-3x3 [mm] "QFN, 12-Leads, Body 4.0x4.0mm (max), Pitch 0.50mm, IPC Low Density"
  rect 0.8x0.25 smd: 1(-1.5,1) 2(-1.5,0.5) 3(-1.5,0) 4(-1.5,-0.5) 5(-1.5,-1) 6(1.5,-1) 7(1.5,-0.5) 8(1.5,0) 9(1.5,0.5) 10(1.5,1)
  rect 0.25x0.8 smd: 11(-0.25,1.3) 11(-0.25,-1.3) 11(0.25,1.3) 11(0.25,-1.3)
  rect 1.65x2.4 smd: 11(0,0)
  silkscreen extent -2.37,-1.5 1.5,1.5
XH2.54mm-10R0x7R0--zhizhen [mm]
  rect 1.6x1.6 hole 1: 1(0,0)
  round 1.6 hole 1: 2(2.54,0) 3(5.08,0)
  silkscreen extent -3.31,-2.1 7.5,3.7

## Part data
C1 C2 C3 C4 C5 C6 C7 C8 C11 C12 C16 C24 C26 C27 C28 C29 C30 C31 C45 C46 C48 C52 C54 C56 C57 C61 C63 C65 C73 C75 C77 C82 C88 C89 C93 C95 C100 C101 C104 C106: library part 0.1uF贴片电容, "贴片电容_GRM188R71H104KA01D_0.1uF±10%,50V,0603"
C9 C10 C17 C19 C25 C32 C53 C60 C62 C78 C81 C92 C94 C103 C105: library part 10uF贴片电容, "贴片电容_GRM188R60J106ME47D_10uF±20%,6.3V,0603"
C13 C74 C76: library part 1uF贴片电容, "贴片电容_GRM188R61A105KA61D_1uF±10%,10V,0603"
C14 C15 C20 C21 C47 C66 C67 C68 C79 C80 C91 C96 C113: library part 10uF贴片电容, "贴片电容_GRM21BR61A106KE19L_10uF±10%,10V,0805"
C18 C22 C23 C43 C51 C69 C71 C83 C84 C85 C87 C90 C99 C102 C107 C108 C109 C110 C111 C112: "GRM188R71H104KA01D"
C33 C40: library part 0.1uF贴片电容, "贴片电容_10nF±10%,50V,0603"
C34: library part 27nF贴片电容, "贴片电容_22nF±5%,50V,0603"
C35 C37: library part 20pF贴片电容, "贴片电容_18pF±5%,50V,0603"
C36 C39: library part 1000pF贴片电容, "贴片电容_GRM188R71H102KA01_1000pF±10%,50V,0603"
C38: library part 1uF贴片电容, "贴片电容_4.7uF±10%,50V,0603"
C41 C42: library part 10uF贴片电容, "贴片电容_1000pF/2KV"
C44 C55: library part 220pF贴片电容, "贴片电容_100pF±10%,50V,0603"
C49 C50 C58 C59: library part 100pF贴片电容, "贴片电容_GRM2165C1H101JA01D_100pF±5%,50V,0805"
C64: "贴片电解电容_VEJ101M1JTR-1010_100uF/63V,±20%,表贴D10*H10"
C70 C98: library part 0.1uF
C72: "贴片电解电容_VE102M1CTR-1010_1000uF/16V,±20%,表贴10*10"
C86: library part 10pF贴片电容, "贴片电容_0603CG100J500NT_10pF±5%,50V,0603"
C97: library part 0.1uF, "0603,10NF,50V,±10％,X7R"
D1: library part 肖特基整流二极管_SS36, "肖特基整流二极管_SS36_封装SMA,3A/60V"
D2: library part 肖特基整流二极管_SS36, "肖特基整流二极管_SL02_1.1A/20V"
FB1 FB3 FB4 FB5 FB6 FB7 FB8 FB9 L1 L2 L3 L5 L6 L7 L8 L9 L10 L12 L13: library part 0805贴片磁珠, "贴片磁珠_600R,0805"
FB2: library part 0603贴片磁珠, "贴片磁珠_100R,0603"
FB11: library part 1206贴片磁珠, "贴片磁珠_30R,6A,1206"
FC1: library part M4穿心电容, "穿心电容_CT52-2-63V-2200PF_M4,2200PF,63V"
J1: library part KF2510-7P连接器, "连接器_KF2510-7P_直插,间距2.54mm"
J2: "连接器_XH2.54-3P_弯针,间距2.54mm"
J3: "Header, 4-Pin"
J4: library part RJ45弯脚带灯, "RJ45插座_1*1,带左黄右绿灯,弯脚"
J7: library part DB2公头座子, "连接器_DB2公头,电源接头"
L4: library part 100uH贴片功率电感, "贴片功率电感_SLF12575T-101M1R9-PF_100uH±20%,额定电流1.9A,12.5x12.5"
L11: library part SLF6025T-100M1R0-PF, "SPM3010T-4R7M-LR"
Q1: "NPN三极管_MMBT2222_表贴SOT23"
R1 R2 R3 R6 R24 R39 R41 R49 R53 R54: library part 4.7K贴片电阻, "贴片电阻_4.7K±5%,0603"
R4 R85: library part 10K贴片电阻, "贴片电阻_10K±5%,0603"
R8 R10 R15 R55 R56 R57 R58 R59 R60 R61 R69 R84 R88 R93 R94 R100 R101 R123: library part 1K贴片电阻, "贴片电阻_1K±5%,0603"
R9 R16 R17 R18 R19 R40 R42 R43 R44: library part 30Ω贴片电阻, "贴片电阻_30Ω±5%,0603"
R22 R25 R27: library part 10Ω贴片电阻
R23 R38: library part 10Ω贴片电阻, "贴片电阻_10Ω±5%,0603"
R26 R28 R29 R30 R31 R32 R45 R50: library part 300Ω贴片电阻, "贴片电阻_300Ω±5%,0603"
R33 R62 R68 R70 R76 R77 R87: library part 0Ω贴片电阻, "贴片电阻_0Ω±5%,0603"
R34 R36: library part 51Ω贴片电阻, "贴片电阻_49.9Ω±1%,0603"
R35 R37: library part 51Ω贴片电阻, "贴片电阻_82Ω±1%,0603"
R46 R48: library part 75Ω贴片电阻, "贴片电阻_75Ω±5%,0805"
R47: library part 1M贴片电阻, "贴片电阻_1M±5%,0603"
R51: library part 75Ω贴片电阻, "贴片电阻_75Ω±5%,1206"
R52: library part 12K贴片电阻, "贴片电阻_12.4K±1%,0603"
R63: library part 300Ω贴片电阻
R64 R65 R72 R73: library part 62Ω贴片电阻
R66 R74: library part 51Ω贴片电阻, "贴片电阻_51Ω±5%,0805"
R67 R75: library part 0Ω贴片电阻
R71: library part 300Ω贴片电阻, "贴片电阻_300Ω±5%,0805"
R78 R79 R89 R90 R97 R98 R110 R111: library part 0.004Ω检流电阻-大封装, "贴片电阻_LR12DTDSR004_0.004±5%,2W,2512"
R80: library part 6.2K贴片电阻, "贴片电阻_6.2K±5%,0603"
R82: library part 2K贴片电阻, "贴片电阻_2K±5%,0603"
R83: library part 12.4K贴片电阻
R86: library part 1.5K贴片电阻, "贴片电阻_1.5K±5%,0603"
R118 R119 R126 R127 R131 R132: library part 1.5K贴片电阻, "贴片电阻_4.7K±5%,0603"
SMA1 SMA2: "射频同轴连接器_SMA-50KFD-4"
T1: "网络变压器_HX1188NL_百兆,SOIC16"
U1: "EEPROM_AT24C02N_SOIC8"
U2: "MCU_STM32F103RCT6_32bit,LQFP64"
U3: library part 拨码开关, "拨码开关_2.54mm-6P_侧拨"
U4 U11: "LDO_LM1117S-3.3_1A输出,SOT223"
U5: "以太网控制器_W5500_LQFP48"
U6: "运算放大器_LM358_SOIC8"
U7 U8: "检波器_AD8361ARMZ_LF to 2.5 GHz,SOIC8"
U9: "稳压集成电路_LM2576HVDP-ADJ_3A输出,SOIC8"
U10: "负压转换器_TPS63700DRCR_360mA输出,VSON-10"
U12: "P-MOSFET_IRF7240TR_SOIC8"
U14 U15 U18 U19: "电流检测放大器_MAX4080TASA_SOIC8"
X1: library part 16M贴片有源晶振, "贴片有源晶振_8M,20ppm,封装5x7"
X2: library part 25M贴片无源晶体, "贴片无源晶体_25MHz,30ppm,6035封装"

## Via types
v1: diameter 0.508, hole 0.305, Top Layer to Bottom Layer, tented both sides, 866 vias
v2: diameter 0.457, hole 0.305, Top Layer to Bottom Layer, tented both sides, 327 vias
v3: diameter 0.66, hole 0.406, Top Layer to Bottom Layer, tented both sides, 200 vias
v4: diameter 0.813, hole 0.508, Top Layer to Bottom Layer, tented both sides, 13 vias
v5: diameter 4.2, hole 2.2, Top Layer to Bottom Layer, 10 vias
v6: diameter 0.6, hole 0.3, Top Layer to Bottom Layer, tented both sides, 7 vias
v7: diameter 4/2.2/2.2/3.5 (per signal layer), hole 2.2, Top Layer to Bottom Layer, 2 vias
v8: diameter 4.191, hole 2.2, Top Layer to Bottom Layer, 1 vias
v9: diameter 0.508, hole 0.3, Top Layer to Bottom Layer, tented both sides, 1 vias
v10: diameter 0.762, hole 0.508, Top Layer to Bottom Layer, tented both sides, 1 vias

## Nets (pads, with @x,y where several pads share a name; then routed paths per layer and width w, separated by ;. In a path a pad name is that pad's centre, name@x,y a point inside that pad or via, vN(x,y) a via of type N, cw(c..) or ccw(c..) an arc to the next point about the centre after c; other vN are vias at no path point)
3.3VADD: C26.2 C27.2 C28.2 C29.2 C30.2 C31.2 C32.2 FB1.2 R34.2 R36.2 R38.2 U5.4 U5.8 U5.11 U5.15 U5.17 U5.21 | length 58.2
  Top Layer w0.254: R38.2@82.536,21.342 83.902,21.342 84.303,21.742 91.516,21.742 v1(91.643,21.615) ; C29.2@91.095,14.414 91.68,14.414 92.605,15.339 U5.11@93.616,15.339 ; C31.2@91.289,19.113 v1(91.657,19.113) 91.931,18.839 U5.4@93.616,18.839 ; v1(91.643,16.954) 92.163,16.954 92.278,16.839 U5.8@93.616,16.839 ; C28.2@96.338,9.93 96.366,9.958 v1(96.366,10.693) U5.15@96.366,13.089 ; U5.17@97.366,13.089 v1(97.366,10.693) 97.366,10.045 C27.2@97.481,9.93 ; U5.21@99.366,13.089 99.366,11.157 v6(99.767,10.756) C26.2@99.767,9.93
  Top Layer w0.381: C29.2@90.94,14.414 C32.2@90.94,13.144 90.979,13.183 v1(91.643,13.183)
  Top Layer w0.635: R36.2@82.536,18.669 R38.2@82.536,21.342
  Top Layer w0.762: v10(106.629,9.754) 106.629,10.904 FB1.2@106.752,11.028
  S3 w0.381: v1@91.643,19.113 v1(91.643,21.615) v1@91.657,21.602
  S3 w0.508: v1(91.657,19.113) 91.657,11.509 92.409,10.756 v6(99.767,10.756) 100.77,9.754 v10(106.629,9.754)
3.3VCC: C1.2 C3.2 C4.2 C5.2 C6.2 C7.2 C8.2 C9.2 C12.1 C60.2 C76.2 C78.2 FB2.2 J3.4 R1.2 R2.2 R3.2 R6.2 U1.8 U2.1 U2.13 U2.19 U2.32 U2.48 U2.64 U11.2 | length 116.2
  Top Layer w0.254: C5.2@116.459,15.963 116.637,16.141 v1(116.637,16.815) 116.637,17.704 116.748,17.815 U2.48@117.489,17.815 ; C3.2@119.214,29.464 119.644,29.034 U2.32@119.644,27.463 ; 119.644,28.692 U2.32@119.644,27.463 ; U2.64@127.137,15.66 127.137,14.722 127.762,14.097 128.944,14.097 ; C7.2@128.458,28.575 128.154,28.88 126.467,28.88 126.144,28.557 U2.19@126.144,27.463 126.144,24.511 ; U2.1@129.292,17.815 130.003,17.815 130.59,17.228 C4.2@130.59,15.963 ; C8.2@131.971,23.814 U2.13@129.292,23.814 126.84,23.814 126.144,24.511 ; C8.2@132.25,23.687 C8.2@132.344,23.594 ; R6.2@132.539,15.963 R6.2@132.627,15.875 ; FB2.2@147.43,22.032 C12.1@147.43,23.374 148.457,23.374 148.971,22.86 148.971,17.577 ; U2.32@119.644,27.463 119.644,25.517 120.65,24.511 126.144,24.511
  Top Layer w0.381: C1.2@123.786,9.745 R2.2@125.181,9.745 124.943,9.506 U1.8@124.943,7.5 ; U1.8@124.943,7.373 U1.8@124.943,7.5 ; C6.2@128.871,12.954 R3.2@128.871,11.518 129.604,11.518 130.175,10.947 130.175,5.842 129.667,5.334 125.222,5.334 124.943,5.613 U1.8@124.943,7.5 ; C4.2@130.717,15.963 R6.2@132.539,15.963 ; C8.2@132.344,23.622 v1(132.344,24.257) C9.2@132.344,24.892 ; R1.2@134.044,22.322 v1(134.747,22.322)
  Top Layer w0.508: J3.4@144.78,16.002 146.228,17.45 U11.2@154.715,17.45
  Bottom Layer w0.381: v1(116.637,16.815) 118.085,15.367 v1(128.93,15.367) 131.357,15.367 132.344,16.354 132.344,18.11 ; v1(132.344,24.257) 132.344,22.322 ; v1(134.747,22.322) 132.344,22.322 ; J3.4@144.78,16.002 142.672,18.11 132.344,18.11 ; 132.344,18.11 132.344,22.322
3.3VCC1: C13.2 C17.2 C19.2 C24.2 C25.2 C87.2 FB1.1 L1.2 L2.2 R24.1 R39.2 R41.2 R49.2 R53.2 R54.2 R118.2 R119.2 R126.2 R127.2 R131.2 R132.2 U4.2 U5.28 | length 118.9
  Top Layer w0.254: U5.28@102.616,16.339 106.39,16.339 C24.2@106.41,16.319
  Top Layer w0.381: R49.2@93.697,27.329 R53.2@94.967,27.329 R54.2@96.237,27.329 96.241,27.332 v1(96.241,28.053) ; v1(103.505,24.333) 104.052,24.333 R39.2@104.165,24.447 ; FB1.1@106.41,13.57 C25.2@106.41,15.144 C24.2@106.41,16.319
  Top Layer w0.508: C87.2@112.561,13.335 112.561,12.229 v1(112.573,12.217) ; R118.2@133.016,12.972 R126.2@135.429,12.972 ; R131.2@137.969,12.972 R119.2@140.509,12.972 ; R127.2@143.049,12.972 145.669,12.972 C19.2@146.558,12.972 ; R132.2@144.827,12.972 R132.2@144.882,12.972
  Top Layer w0.635: FB1.1@106.752,13.228 v4(107.829,13.228) ; R41.2@108.11,18.859 v1(108.835,18.859)
  Top Layer w0.762: L2.2@90.943,11.557 92.659,11.557 v4(93.32,12.217)
  Bottom Layer w0.381: v1(96.241,28.053) 96.241,24.765 96.672,24.333 v1(103.505,24.333) ; 106.422,18.859 v1(108.835,18.859)
  Bottom Layer w0.508: v1(103.505,24.333) 105.512,24.333 106.422,23.423 106.422,18.859 v6(106.422,15.769) 106.422,12.29
  Bottom Layer w0.762: v4(93.32,12.217) v1(112.573,12.217) 133.409,12.217 v1(134.163,12.972) v1@145.661,12.972 ; 107.829,12.292 v4(107.829,13.228) ; v1(145.669,12.979) 147.371,11.278 156.058,11.278 v4(157.505,9.83)
  other v1: 139.243,12.972
3.3VCC11: J1.1 J4.10 J4.12 L2.1 | length 41.3
  Top Layer w0.381: J4.10@54.123,2.734 55.834,4.445 64.843,4.445 ; J4.12@64.843,2.734 64.843,4.445 ; J1.1@72.517,7.208 71.151,5.842 67.615,5.842 66.218,4.445 64.843,4.445
  Top Layer w0.762: J1.1@72.568,7.259 J1.1@72.517,7.208 72.517,8.687 73.355,9.525 87.111,9.525 L2.1@89.143,11.557
28VIN: C64.1 C65.2 C88.2 C89.2 C100.2 C101.2 J7.1 J7.2 R78.1 R79.1 R83.1 R89.1 R90.1 R97.1 R98.1 R110.1 R111.1 U9.1 U14.1 U14.2 U15.1 U15.2 U18.1 U18.2 U19.1 U19.2 | length 18
  Top Layer w0.381: R83.1@131.406,31.666 v1(131.406,32.651)
  Top Layer w1.5: C64.1@27.178,11.217 27.178,3.683 28.448,2.413 35.941,2.413 36.068,2.54
  other v3: 9.555,6.083 11.516,6.083 13.477,6.083 15.437,6.083 17.398,6.083 19.359,6.083 21.319,6.083 9.555,7.659 11.516,7.659 13.477,7.659 15.437,7.659 17.398,7.659 19.359,7.659 21.319,7.659 9.555,9.235 11.516,9.235 13.477,9.235 15.437,9.235 17.398,9.235 19.359,9.235 21.319,9.235 9.555,10.811 11.516,10.811 13.477,10.811 15.437,10.811 17.398,10.811 19.359,10.811 21.319,10.811 9.555,12.387 11.516,12.387 13.477,12.387 15.437,12.387 17.398,12.387 19.359,12.387 21.319,12.387 9.555,13.963 11.516,13.963 13.477,13.963 15.437,13.963 17.398,13.963 19.359,13.963 21.319,13.963 9.555,15.54 11.516,15.54 13.477,15.54 15.437,15.54 17.398,15.54 19.359,15.54 21.319,15.54 9.555,17.116 11.516,17.116 13.477,17.116 15.437,17.116 17.398,17.116 19.359,17.116 21.319,17.116 9.555,18.692 11.516,18.692 13.477,18.692 15.437,18.692 17.398,18.692 19.359,18.692 21.319,18.692 9.555,20.268 11.516,20.268 13.477,20.268 15.437,20.268 17.398,20.268 19.359,20.268 21.319,20.268 9.379,32.762 10.695,32.762 12.011,32.762 13.328,32.762 14.644,32.762 15.96,32.762 17.276,32.762 18.745,32.963 21.793,32.963 82.88,32.963 85.928,32.963 148.793,32.963 151.841,32.963 213.411,32.963 216.459,32.963 80.416,32.988 146.202,32.988 210.82,32.988 81.686,33.812 147.472,33.812 212.09,33.812 18.745,33.921 21.793,33.921 82.88,33.921 85.928,33.921 148.793,33.921 151.841,33.921 213.411,33.921 216.459,33.921 80.416,33.946 146.202,33.946 210.82,33.946 9.379,34.224 10.695,34.224 12.011,34.224 13.328,34.224 14.644,34.224 15.96,34.224 17.276,34.224 81.686,34.77 147.472,34.77 212.09,34.77 18.745,34.878 21.793,34.878 82.88,34.878 85.928,34.878 148.793,34.878 151.841,34.878 213.411,34.878 216.459,34.878 80.416,34.904 146.202,34.904 210.82,34.904 9.379,35.685 10.695,35.685 12.011,35.685 13.328,35.685 14.644,35.685 15.96,35.685 17.276,35.685 81.686,35.727 147.472,35.727 212.09,35.727 18.745,35.836 21.793,35.836 82.88,35.836 85.928,35.836 148.793,35.836 151.841,35.836 213.411,35.836 216.459,35.836 80.416,35.862 146.202,35.862 210.82,35.862 81.686,36.685 147.472,36.685 212.09,36.685 18.745,36.794 21.793,36.794 82.88,36.794 85.928,36.794 148.793,36.794 151.841,36.794 213.411,36.794 216.459,36.794 80.416,36.819 146.202,36.819 210.82,36.819 9.379,37.147 10.695,37.147 12.011,37.147 13.328,37.147 14.644,37.147 15.96,37.147 17.276,37.147 81.686,37.643 147.472,37.643 212.09,37.643 18.745,37.752 21.793,37.752 82.88,37.752 85.928,37.752 148.793,37.752 151.841,37.752 213.411,37.752 216.459,37.752 80.416,37.777 146.202,37.777 210.82,37.777 9.379,38.608 10.695,38.608 12.011,38.608 13.328,38.608 14.644,38.608 15.96,38.608 17.276,38.608 81.686,38.601 147.472,38.601 212.09,38.601 18.745,38.71 21.793,38.71 82.88,38.71 85.928,38.71 148.793,38.71 151.841,38.71 213.411,38.71 216.459,38.71 80.416,38.735 146.202,38.735 210.82,38.735
28VOUT1: R78.2 R89.2 U14.8
28VOUT2: R97.2 R110.2 U18.8
28VOUT3: R79.2 R90.2 U15.8
28VOUT4: R98.2 R111.2 U19.8
+5V: C14.2 C15.2 C16.2 C44.1 C45.1 C46.1 C47.1 C48.2 C55.1 C56.1 C57.2 C67.2 C74.1 C77.2 C79.2 C80.2 C91.2 C98.2 FB11.2 L5.1 R23.1 U4.3 U6.8 U7.1 U7.2 U8.1 U8.2 U10.5 U11.3 | length 136.7
  Top Layer w0.254: U10.5@168.208,6.018 168.861,6.018 169.367,5.512 C98.2@169.367,4.597
  Top Layer w0.381: C48.2@201.383,18.457 v1(202.133,18.457) 203.683,18.457 204.016,18.457 C45.1@204.089,18.53 ; C44.1@203.175,18.457 203.175,15.723 ; U7.1@204.727,14.967 203.473,14.967 203.175,15.265 203.175,15.723 ; U7.2@204.727,15.617 203.28,15.617 203.175,15.723 ; C55.1@225.196,18.457 225.196,15.164 225.552,14.808 U8.1@226.906,14.808 ; 225.211,15.458 U8.2@226.906,15.458
  Top Layer w0.508: C47.1@180.88,11.366 v1(181.762,11.366) 184.192,11.366 184.571,11.744 U6.8@184.571,12.846 ; C57.2@222.973,18.457 v1(223.672,18.457) 225.511,18.457 C55.1@225.584,18.53
  Top Layer w0.635: 154.864,5.715 158.42,5.715 162.865,1.27 169.682,1.27 C67.2@169.534,1.418 169.482,1.47 C98.2@169.482,4.445 ; 165.088,1.43 R23.1@165.088,2.87 ; v4(181.762,17.876) C74.1@186.294,17.876
  Top Layer w0.762: U11.3@154.715,15.15 154.932,15.367 156.337,15.367 156.894,15.924 v4(156.894,21.082) FB11.2@156.894,22.987
  S3 w0.381: 181.847,18.457 v1(202.133,18.457) v1(223.672,18.457)
  S3 w0.635: v4(156.894,21.082) 179.959,21.082 181.762,19.279 v4(181.762,17.876) v1(181.762,11.366)
+5V_0: C69.2 C70.2 FB3.1 FB5.1 FB6.1 FB7.1 FB8.2 | length 219.6
  Top Layer w0.381: v1(41.91,29.083) FB3.1@41.91,32.704 ; v1(106.68,29.337) FB5.1@106.68,32.577 ; v4(171.704,29.337) FB6.1@171.704,32.577 ; v1(236.593,28.025) 236.601,28.016 FB7.1@236.601,32.628
  Top Layer w0.762: FB8.2@171.693,22.733 171.704,22.744 v1(171.704,25.095) v4(171.704,29.337)
  S3 w0.381: v1(41.91,29.083) 70.764,29.083 72.669,27.178 85.492,27.178 87.642,29.328 v1@106.68,29.328 ; v1(171.704,25.095) 172.491,24.308 180.366,24.308 182.778,26.721 212.7,26.721 214.003,28.025 v1(236.593,28.025) v1@236.601,28.016
  S3 w0.508: v1(106.68,29.337) v4(171.704,29.337)
+5V_1: C71.2 FB3.2
+5V_2: C83.2 FB5.2
+5V_3: C102.2 FB6.2
+5V_4: C107.2 FB7.2
-5V: C112.2 C113.2 FB4.2 L7.1 L8.1 L9.1 L10.1 | length 220.8
  Top Layer w0.381: v1(37.084,28.111) L7.1@37.084,32.704 ; L8.1@103.505,32.577 103.505,29.743 v1(105.08,28.169) ; v4(167.259,28.169) L9.1@167.259,32.577 ; v1(232.004,28.981) 232.004,32.603 L10.1@232.029,32.628
  Top Layer w0.635: L9.1@167.259,32.377 L9.1@167.259,32.504
  Top Layer w0.889: FB4.2@167.259,22.479 v4(167.259,28.169)
  S3 w0.381: v1(37.084,28.111) 68.917,28.111 70.739,26.289 86.868,26.289 87.503,26.924 102.159,26.924 103.403,28.169 v1(105.08,28.169) ; v2(167.259,27.051) 180.213,27.051 182.143,28.981 v1(232.004,28.981)
  S3 w0.508: v1(105.08,28.169) v4(167.259,28.169)
-5V_00: C20.2 C21.2 C66.2 C96.2 C99.2 D2.1 FB4.1 R25.1 R27.1 U10.8 | length 5
  Top Layer w0.305: U10.8@167.208,9.018 167.208,13.995
ACTLED: R45.2 U5.27 | length 22.9
  Top Layer w0.254: R45.2@94.957,8.156 94.957,7.1 95.225,6.833 105.283,6.833 105.461,7.01 105.461,15.011 104.634,15.839 U5.27@102.616,15.839
AT_DAC: U2.21
BD_TEMP: J2.2 R24.2 U2.51 | length 14.1
  Top Layer w0.254: R24.2@114.998,12.014 118.542,12.014 120.637,14.109 U2.51@120.637,15.66
  Top Layer w0.381: J2.2@113.665,6.477 113.665,8.661 114.998,9.994 R24.2@114.998,12.014
COMM_LED: R32.2 U2.62 | length 46.6
  Top Layer w0.254: R32.2@94.703,1.778 v1(107.569,1.778) ; U2.62@126.137,15.66 126.137,14.706 v1(126.797,14.046) v1@126.873,13.97
  S3 w0.254: v1(107.569,1.778) 107.569,8.814 108.382,9.627 117.043,9.627 117.907,10.49 v1(117.907,14.402)
  Bottom Layer w0.254: v1(117.907,14.402) 118.948,14.402 ; 118.339,14.402 118.948,14.402 ; v1@126.873,13.97 v1(126.797,14.046) 126.441,14.402 118.948,14.402
CPU_USERCLK: R9.2 U2.5 | length 2.8
  Top Layer w0.254: U2.5@129.292,19.814 R9.2@131.985,19.814 ; R9.2@132.264,19.687 R9.2@132.369,19.792
CURR_LED: R30.2 U2.57 | length 39.1
  Top Layer w0.254: R30.2@94.703,3.454 108.687,3.454 109.855,2.286 117.373,2.286 120.142,5.055 120.142,9.728 123.637,13.223 U2.57@123.637,15.66
DUPLED: U5.26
